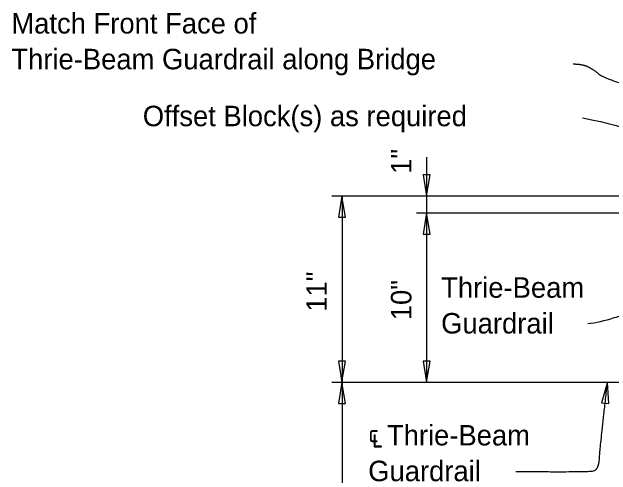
# Model space of a CAD drawing. Extents: x 21516.9 to 21589, y 56156.6 to 56194.3.
# Drawn here: x 21539.41 to 21545.31, y 56185.8 to 56190.36 of the extents above; entities that cross this region are included whole.
import ezdxf

# ---------------------------------------------------------------- set-up
doc = ezdxf.new("R2010")
doc.units = 0
for name, color, linetype in [('Patterning', 7, 'Continuous'), ('PlotBorder_dp', 7, 'Continuous'), ('SheetBorder_dp', 7, 'Continuous')]:
    doc.layers.add(name, color=color, linetype=linetype)

msp = doc.modelspace()

# ---------------------------------------------------------------- linework, layer by layer
at = {"layer": 'Patterning'}
msp.add_line((21542.5627, 56186.7118), (21546.079, 56186.7118), dxfattribs=at)
at = {"layer": 'PlotBorder_dp'}
for p, q in [((21543.4961, 56188.9295), (21543.4961, 56186.7118)), ((21546.1124, 56188.5451), (21542.5627, 56188.5451)), ((21542.6627, 56188.5451), (21542.6627, 56181.4587)), ((21546.1124, 56188.3784), (21543.3961, 56188.3784))]:
    msp.add_line(p, q, dxfattribs=at)
for points in [[(21543.4961, 56188.5451), (21543.5313, 56188.7534), (21543.4608, 56188.7534)], [(21542.6626, 56188.5451), (21542.6274, 56188.3369), (21542.6979, 56188.3369)], [(21543.4961, 56188.3785), (21543.4608, 56188.1702), (21543.5313, 56188.1702)], [(21542.6626, 56186.7118), (21542.6979, 56186.9201), (21542.6274, 56186.9201)], [(21543.4961, 56186.7118), (21543.5313, 56186.9201), (21543.4608, 56186.9201)], [(21542.6626, 56186.7118), (21542.6274, 56186.5035), (21542.6979, 56186.5035)], [(21545.2771, 56186.7128), (21545.2182, 56186.51), (21545.2883, 56186.5019)]]:
    msp.add_lwpolyline(points, close=True, dxfattribs=at)
for points, degree in [([(21544.9392, 56189.8454), (21545.0243, 56189.8454), (21545.1321, 56189.7971), (21545.2569, 56189.6922), (21545.6313, 56189.5901)], 2), ([(21545.0299, 56189.3149), (21545.553, 56189.2123), (21545.7535, 56189.066), (21545.811, 56188.9533), (21546.404, 56188.4613), (21546.6161, 56188.2827)], 3), ([(21545.084, 56187.2897), (21545.1627, 56187.2989), (21545.3328, 56187.3399), (21545.5453, 56187.4167), (21545.9287, 56187.6685)], 3), ([(21544.3744, 56185.8346), (21545.0823, 56185.828), (21545.1912, 56185.8511), (21545.2044, 56186.0822), (21545.277, 56186.7129)], 2)]:
    msp.add_open_spline(points, degree=degree, dxfattribs=at)

# ---------------------------------------------------------------- texts
for s, p in [('Match Front Face of ', (21539.4075, 56190.1448)), ('Thrie-Beam Guardrail along Bridge', (21539.4075, 56189.7928)), ('Thrie-Beam', (21543.6389, 56187.5443)), ('Guardrail', (21543.6389, 56187.1923)), ('℄ Thrie-Beam', (21542.9208, 56186.0903)), ('Guardrail', (21542.9208, 56185.7383))]:
    msp.add_text(s, height=0.2016, dxfattribs=at).set_placement(p)
at = {"layer": 'SheetBorder_dp'}
msp.add_text('Offset Block(s) as required ', height=0.2016, dxfattribs=at).set_placement((21540.7015, 56189.2326))
for s, p in [('1"', (21543.3461, 56188.7637)), ('11"', (21542.5127, 56187.4065)), ('10"', (21543.3461, 56187.3232))]:
    msp.add_text(s, height=0.2016, rotation=90, dxfattribs=at).set_placement(p)

doc.saveas('drawing.dxf')
